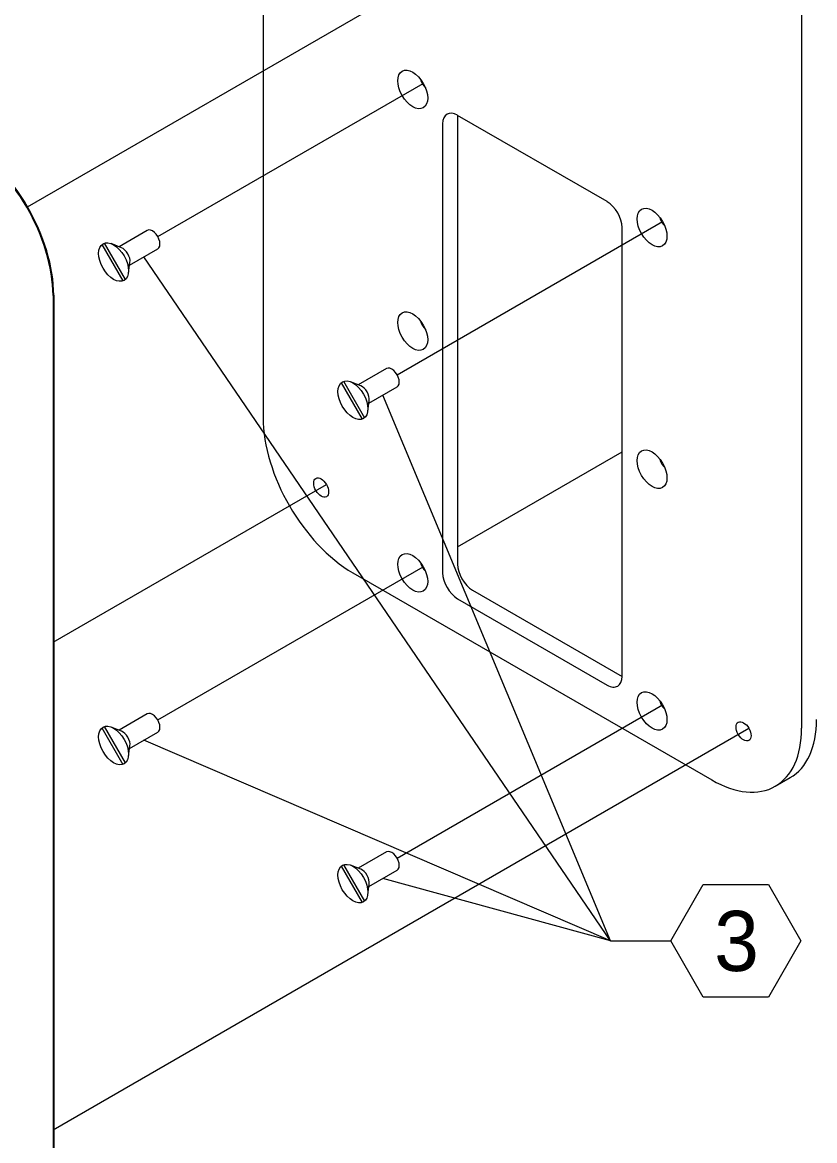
# Model space of a CAD drawing. Extents: x 99862 to 103151, y 100000 to 105076.
# Drawn here: x 100248.4 to 100459.1, y 104386.4 to 104683.9 of the extents above; entities that cross this region are included whole.
import ezdxf

# ---------------------------------------------------------------- set-up
doc = ezdxf.new("R2010")
doc.units = 0
for name, color, linetype in [('Level 15', 7, 'Continuous'), ('Level 16', 7, 'Continuous'), ('Level 20', 7, 'Continuous'), ('Level 40', 7, 'Continuous'), ('Level 41', 7, 'Continuous')]:
    doc.layers.add(name, color=color, linetype=linetype)

msp = doc.modelspace()

# ---------------------------------------------------------------- linework, layer by layer
at = {"layer": 'Level 15'}
for q in [(100280.66, 104621.45), (100344.3, 104584.71), (100280.66, 104492.86), (100344.3, 104456.11), (100420.83, 104439.48)]:
    msp.add_line((100404.83, 104439.48), q, dxfattribs=at)
at = {"layer": 'Level 16'}
for p, q in [((100249.76, 104634.79), (100441.6, 104745.55)), ((100284.41, 104626.87), (100355.02, 104667.63)), ((100348.05, 104590.12), (100418.66, 104630.89)), ((100364.14, 104544.3), (100407.89, 104569.56)), ((100256.55, 104518.93), (100329.27, 104560.91)), ((100284.41, 104498.27), (100355.02, 104539.04)), ((100348.05, 104461.52), (100418.66, 104502.29)), ((100256.55, 104389.21), (100441.6, 104496.05))]:
    msp.add_line(p, q, dxfattribs=at)
at = {"layer": 'Level 20'}
msp.add_lwpolyline([(100420.83, 104439.48), (100429.49, 104454.48), (100446.81, 104454.48), (100455.46, 104439.48), (100446.81, 104424.48), (100429.49, 104424.48), (100420.83, 104439.48)], dxfattribs=at)
at = {"layer": 'Level 40'}
for p, q in [((100256.55, 104611.15), (100256.55, 104381.14)), ((100256.75, 104611.26), (100256.75, 104381.26))]:
    msp.add_line(p, q, dxfattribs=at)
for centre in [(100232.68, 104624.93), (100232.88, 104625.04)]:
    msp.add_ellipse(centre, major_axis=(-16.88, 29.23), ratio=0.57735, start_param=3.926991, end_param=5.497787, dxfattribs=at)
at = {"layer": 'Level 41'}
for p, q in [((100312.43, 104808.75), (100312.43, 104578.75)), ((100455.62, 104726.08), (100455.62, 104496.08)), ((100360.16, 104656.82), (100360.16, 104537.41)), ((100364.14, 104659.12), (100364.14, 104539.71)), ((100403.92, 104636.16), (100364.14, 104659.12)), ((100281.59, 104628.49), (100274.1, 104624.16)), ((100407.89, 104509.86), (100407.89, 104629.27)), ((100269.54, 104624.73), (100275.13, 104615.06)), ((100270.19, 104625.11), (100275.78, 104615.43)), ((100274.74, 104623.91), (100272.04, 104624.98)), ((100276.91, 104619.29), (100284.41, 104623.62)), ((100276.59, 104617.1), (100277.01, 104619.97)), ((100345.23, 104591.75), (100337.74, 104587.42)), ((100333.18, 104587.99), (100338.77, 104578.31)), ((100333.83, 104588.37), (100339.42, 104578.69)), ((100338.38, 104587.16), (100335.68, 104588.23)), ((100340.55, 104582.55), (100348.05, 104586.88)), ((100340.23, 104580.36), (100340.65, 104583.23)), ((100336.3, 104537.41), (100431.76, 104482.3)), ((100368.12, 104532.82), (100407.89, 104509.86)), ((100364.14, 104530.52), (100403.92, 104507.56)), ((100281.59, 104499.89), (100274.1, 104495.56)), ((100269.54, 104496.14), (100275.13, 104486.46)), ((100270.19, 104496.51), (100275.78, 104486.83)), ((100274.74, 104495.31), (100272.04, 104496.38)), ((100276.91, 104490.69), (100284.41, 104495.02)), ((100276.59, 104488.51), (100277.01, 104491.37)), ((100448.63, 104480.63), (100452.61, 104482.92)), ((100345.23, 104463.15), (100337.74, 104458.82)), ((100333.18, 104459.39), (100338.77, 104449.72)), ((100333.83, 104459.77), (100339.42, 104450.09)), ((100338.38, 104458.57), (100335.68, 104459.63)), ((100340.55, 104453.95), (100348.05, 104458.28)), ((100340.23, 104451.76), (100340.65, 104454.63))]:
    msp.add_line(p, q, dxfattribs=at)
for centre, major_axis in [((100352.21, 104666.01), (-2.81, 4.87)), ((100415.85, 104629.27), (-2.81, 4.87)), ((100272.66, 104620.08), (-2.81, 4.87)), ((100352.21, 104601.71), (-2.81, 4.87)), ((100336.3, 104583.34), (-2.81, 4.87)), ((100415.85, 104564.97), (-2.81, 4.87)), ((100327.86, 104560.1), (-1.41, 2.44)), ((100352.21, 104537.41), (-2.81, 4.87)), ((100415.85, 104500.67), (-2.81, 4.87)), ((100272.66, 104491.48), (-2.81, 4.87)), ((100440.19, 104495.24), (-1.41, 2.44)), ((100336.3, 104454.74), (-2.81, 4.87))]:
    msp.add_ellipse(centre, major_axis=major_axis, ratio=0.57735, dxfattribs=at)
for centre, major_axis, start_param, end_param in [((100356.19, 104668.31), (-1.41, 2.44), 1.084101, 2.057491), ((100364.14, 104654.53), (-2.81, 4.87), 5.497787, 7.068583), ((100403.92, 104631.56), (-2.81, 4.87), 3.926991, 5.497787), ((100419.82, 104631.56), (-1.41, 2.44), 1.084101, 2.057491), ((100283, 104626.05), (1.41, -2.44), 6.28318, 9.424778), ((100283, 104626.05), (1.41, -2.44), 3.141593, 3.141605), ((100275.04, 104621.46), (1.41, -2.44), 0.630137, 2.511455), ((100356.19, 104604.01), (-1.41, 2.44), 1.084101, 2.057491), ((100346.64, 104589.31), (1.41, -2.44), 6.28318, 9.424778), ((100346.64, 104589.31), (1.41, -2.44), 3.141593, 3.141605), ((100338.68, 104584.72), (1.41, -2.44), 0.630137, 2.511453), ((100336.3, 104564.97), (16.88, -29.23), 3.926991, 5.497787), ((100419.82, 104567.27), (-1.41, 2.44), 1.084101, 2.057491), ((100356.19, 104539.71), (-1.41, 2.44), 1.084101, 2.057491), ((100364.14, 104535.12), (-2.81, 4.87), 0.785398, 2.356194), ((100368.12, 104537.41), (-2.81, 4.87), 0.785398, 2.356194), ((100403.92, 104512.15), (-2.81, 4.87), 2.356194, 3.926991), ((100419.82, 104502.97), (-1.41, 2.44), 1.084101, 2.057491), ((100283, 104497.46), (1.41, -2.44), 6.28318, 9.424778), ((100283, 104497.46), (1.41, -2.44), 3.141593, 3.141605), ((100431.76, 104509.86), (16.88, -29.23), 6.283185, 7.068583), ((100435.73, 104512.15), (16.88, -29.23), 0, 0.785398), ((100275.04, 104492.86), (1.41, -2.44), 0.630137, 2.511455), ((100431.76, 104509.86), (16.88, -29.23), 5.497787, 6.283185), ((100346.64, 104460.71), (1.41, -2.44), 6.28318, 9.424778), ((100346.64, 104460.71), (1.41, -2.44), 3.141593, 3.141605), ((100338.68, 104456.12), (1.41, -2.44), 0.630137, 2.511455)]:
    msp.add_ellipse(centre, major_axis=major_axis, ratio=0.57735, start_param=start_param, end_param=end_param, dxfattribs=at)

# ---------------------------------------------------------------- texts
at = {"layer": 'Level 20'}
msp.add_text('3', height=16, dxfattribs=at).set_placement((100432.37, 104431.48))

doc.saveas('drawing.dxf')
